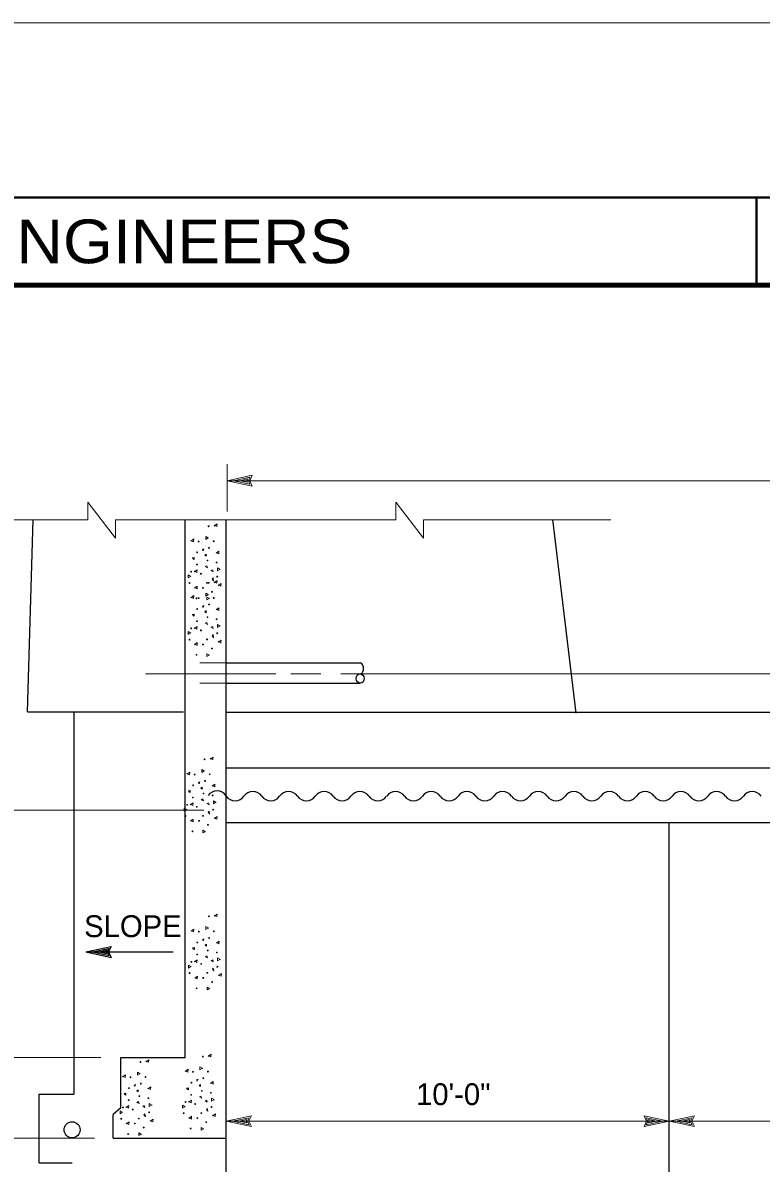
# Model space of a CAD drawing. Extents: x -24.3 to 17.7, y -17.6 to 12.4.
# Drawn here: x -19.54 to -15.32, y 5.87 to 12.39 of the extents above; entities that cross this region are included whole.
import ezdxf
from ezdxf.enums import TextEntityAlignment as Align

# ---------------------------------------------------------------- set-up
doc = ezdxf.new("R2010")
doc.units = 0
doc.header["$LTSCALE"] = 0.05
doc.linetypes.add('MEDIUM_DASHED', pattern=[4.5, 3, -1.5])
doc.layers.add('1', color=7, linetype='Continuous', lineweight=13)
doc.layers.add('2', color=7, linetype='Continuous', lineweight=13)

msp = doc.modelspace()

# ---------------------------------------------------------------- linework, layer by layer
at = {"layer": '1', "lineweight": 40}
msp.add_line((-15.34269, 11.3894), (-15.34269, 10.8894), dxfattribs=at)
at = {"layer": '1'}
for p, q in [((-18.37069, 9.5954), (-18.37069, 9.8654)), ((-18.37069, 9.7704), (-18.22669, 9.8014)), ((-18.33369, 9.7704), (-18.23969, 9.7904)), ((-18.23969, 9.7904), (-18.24869, 9.7704)), ((-18.37069, 9.7704), (-18.22669, 9.7394)), ((-18.37069, 9.7704), (-12.85569, 9.7704)), ((-18.33369, 9.7704), (-18.23969, 9.7504)), ((-18.29769, 9.7704), (-18.25269, 9.7804)), ((-18.29769, 9.7704), (-18.25269, 9.7614)), ((-18.25269, 9.7804), (-18.25669, 9.7704)), ((-18.25669, 9.7704), (-18.25269, 9.7614)), ((-18.24869, 9.7704), (-18.23969, 9.7504)), ((-19.16669, 9.5474), (-19.16669, 9.6474)), ((-19.00869, 9.4424), (-19.16669, 9.6474)), ((-17.40469, 9.5474), (-17.40469, 9.6474)), ((-17.24669, 9.4424), (-17.40469, 9.6474)), ((-19.72169, 9.5474), (-19.16669, 9.5474)), ((-19.00869, 9.4424), (-19.00869, 9.5474)), ((-19.00869, 9.5474), (-17.40469, 9.5474)), ((-17.24669, 9.4424), (-17.24669, 9.5474)), ((-17.24669, 9.5474), (-16.17469, 9.5474)), ((-18.83669, 8.6664), (-18.09169, 8.6664)), ((-18.00569, 8.6664), (-17.83369, 8.6664)), ((-17.71969, 8.6664), (-13.15669, 8.6664)), ((-18.50269, 7.8864), (-21.16869, 7.8864)), ((-19.09169, 6.4724), (-20.31569, 6.4724)), ((-18.37569, 6.1074), (-18.23169, 6.1384)), ((-15.84169, 6.1074), (-15.98569, 6.1384)), ((-15.84169, 6.1074), (-15.69769, 6.1384)), ((-18.37569, 6.1074), (-18.23169, 6.0764)), ((-18.33869, 6.1074), (-18.24469, 6.1274)), ((-18.33869, 6.1074), (-18.24469, 6.0874)), ((-18.30269, 6.1074), (-18.25769, 6.1174)), ((-18.30269, 6.1074), (-18.25769, 6.0984)), ((-18.25769, 6.1174), (-18.26169, 6.1074)), ((-18.26169, 6.1074), (-18.25769, 6.0984)), ((-18.24469, 6.1274), (-18.25369, 6.1074)), ((-18.25369, 6.1074), (-18.24469, 6.0874)), ((-15.84169, 6.1074), (-15.98569, 6.0764)), ((-15.87869, 6.1074), (-15.97269, 6.1274)), ((-15.96369, 6.1074), (-15.97269, 6.1274)), ((-15.87869, 6.1074), (-15.97269, 6.0874)), ((-15.97269, 6.0874), (-15.96369, 6.1074)), ((-15.91469, 6.1074), (-15.95969, 6.1164)), ((-15.95569, 6.1074), (-15.95969, 6.1164)), ((-15.91469, 6.1074), (-15.95969, 6.0974)), ((-15.95969, 6.0974), (-15.95569, 6.1074)), ((-15.84169, 6.1074), (-15.69769, 6.0764)), ((-15.80469, 6.1074), (-15.71069, 6.1274)), ((-15.80469, 6.1074), (-15.71069, 6.0874)), ((-15.76869, 6.1074), (-15.72369, 6.1174)), ((-15.76869, 6.1074), (-15.72369, 6.0984)), ((-15.72369, 6.1174), (-15.72769, 6.1074)), ((-15.72769, 6.1074), (-15.72369, 6.0984)), ((-15.71069, 6.1274), (-15.71969, 6.1074)), ((-15.71969, 6.1074), (-15.71069, 6.0874)), ((-19.12869, 6.0104), (-20.37669, 6.0104))]:
    msp.add_line(p, q, dxfattribs=at)
at = {"layer": '1', "lineweight": 25}
for p, q in [((-19.51169, 8.4484), (-19.47869, 9.5474)), ((-18.61069, 6.4724), (-18.61069, 9.5474)), ((-18.37569, -0.0986), (-18.37569, 9.5474)), ((-16.37369, 8.4404), (-16.50769, 9.5484)), ((-18.37569, 8.7284), (-17.60669, 8.7284)), ((-18.37569, 8.6124), (-17.60869, 8.6124)), ((-19.51169, 8.4484), (-18.61969, 8.4484)), ((-19.24569, 6.2664), (-19.24569, 8.4484)), ((-18.37569, 8.4474), (-9.74369, 8.4474)), ((-18.37569, 8.1284), (-9.77669, 8.1284)), ((-18.37569, 7.8164), (-9.81169, 7.8164)), ((-15.84269, 1.6534), (-15.84269, 7.8164)), ((-19.17769, 7.0754), (-19.03369, 7.1064)), ((-19.17769, 7.0754), (-18.67869, 7.0754)), ((-19.17769, 7.0754), (-19.03369, 7.0444)), ((-19.14069, 7.0754), (-19.04669, 7.0954)), ((-19.14069, 7.0754), (-19.04669, 7.0554)), ((-19.10469, 7.0754), (-19.05969, 7.0854)), ((-19.10469, 7.0754), (-19.05969, 7.0664)), ((-19.05969, 7.0854), (-19.06369, 7.0754)), ((-19.06369, 7.0754), (-19.05969, 7.0664)), ((-19.04669, 7.0954), (-19.05569, 7.0754)), ((-19.05569, 7.0754), (-19.04669, 7.0554)), ((-18.97769, 6.1834), (-18.97769, 6.4724)), ((-18.97769, 6.4724), (-18.61069, 6.4724)), ((-19.44569, 5.8694), (-19.44569, 6.2624)), ((-19.44569, 6.2624), (-19.24569, 6.2624)), ((-18.97769, 6.1834), (-19.02269, 6.1454)), ((-19.02269, 6.0104), (-19.02269, 6.1454)), ((-19.02269, 6.0104), (-18.37969, 6.0104)), ((-19.44569, 5.8694), (-19.25569, 5.8694))]:
    msp.add_line(p, q, dxfattribs=at)
at = {"layer": '1', "linetype": 'MEDIUM_DASHED'}
for p, q in [((-18.37569, 8.7284), (-18.61069, 8.7284)), ((-18.37569, 8.6124), (-18.61069, 8.6124))]:
    msp.add_line(p, q, dxfattribs=at)
at = {"layer": '1'}
for points in [[(-24.34269, 12.3894), (17.65731, 12.3894), (17.65731, -17.6106)], [(-18.22669, 9.8014), (-18.24069, 9.7704), (-18.22669, 9.7394)], [(-18.23169, 6.1384), (-18.24569, 6.1074), (-18.23169, 6.0764)], [(-15.98569, 6.0764), (-15.97169, 6.1074), (-15.98569, 6.1384)], [(-15.69769, 6.1384), (-15.71169, 6.1074), (-15.69769, 6.0764)], [(-18.37569, 6.1074), (-15.84169, 6.1074), (-10.82569, 6.1074)]]:
    msp.add_lwpolyline(points, dxfattribs=at)
at = {"layer": '1', "lineweight": 40}
msp.add_lwpolyline([(-23.34269, -16.6106), (-23.34269, 11.3894), (16.65731, 11.3894), (16.65731, -16.6106)], close=True, dxfattribs=at)
at = {"layer": '1', "lineweight": 90}
msp.add_lwpolyline([(-21.84269, 10.8894), (16.15731, 10.8894), (16.15731, -16.1106), (-21.84269, -16.1106)], close=True, dxfattribs=at)
at = {"layer": '1', "lineweight": 25}
msp.add_lwpolyline([(-19.03369, 7.1064), (-19.04769, 7.0754), (-19.03369, 7.0444)], dxfattribs=at)
msp.add_circle((-19.25669, 6.0584), 0.04597, dxfattribs=at)
for centre, radius, start, end in [((-17.62775, 8.69668), 0.03807, 307.28682, 56.4084), ((-18.42769, 7.9349), 0.06157, 34.07719, 145.9228), ((-18.32469, 8.0009), 0.06157, 214.07719, 325.9228), ((-18.22269, 7.9319), 0.06157, 34.07719, 145.9228), ((-18.12069, 8.0009), 0.06157, 214.07719, 325.9228), ((-18.01869, 7.9319), 0.06157, 34.07719, 145.9228), ((-17.91669, 8.0009), 0.06157, 214.07719, 325.9228), ((-17.81469, 7.9319), 0.06157, 34.07719, 145.9228), ((-17.71269, 8.0009), 0.06157, 214.07719, 325.9228), ((-17.61069, 7.9319), 0.06157, 34.07719, 145.9228), ((-17.50869, 8.0009), 0.06157, 214.07719, 325.9228), ((-17.40669, 7.9319), 0.06157, 34.07719, 145.9228), ((-17.30469, 8.0009), 0.06157, 214.07719, 325.9228), ((-17.20269, 7.9319), 0.06157, 34.07719, 145.9228), ((-17.10069, 8.0009), 0.06157, 214.07719, 325.9228), ((-16.99869, 7.9319), 0.06157, 34.07719, 145.9228), ((-16.89669, 8.0009), 0.06157, 214.07719, 325.9228), ((-16.79469, 7.9319), 0.06157, 34.07719, 145.9228), ((-16.69269, 8.0009), 0.06157, 214.07719, 325.9228), ((-16.59069, 7.9319), 0.06157, 34.07719, 145.9228), ((-16.48869, 8.0009), 0.06157, 214.07719, 325.9228), ((-16.38669, 7.9319), 0.06157, 34.07719, 145.9228), ((-16.28469, 8.0009), 0.06157, 214.07719, 325.9228), ((-16.18269, 7.9319), 0.06157, 34.07719, 145.9228), ((-16.08069, 8.0009), 0.06157, 214.07719, 325.9228), ((-15.97869, 7.9319), 0.06157, 34.07719, 145.9228), ((-15.87669, 8.0009), 0.06157, 214.07719, 325.9228), ((-15.77469, 7.9319), 0.06157, 34.07719, 145.9228), ((-15.67269, 8.0009), 0.06157, 214.07719, 325.9228), ((-15.57069, 7.9319), 0.06157, 34.07719, 145.9228), ((-15.46869, 8.0009), 0.06157, 214.07719, 325.9228), ((-15.36669, 7.9319), 0.06157, 34.07719, 145.9228)]:
    msp.add_arc(centre, radius, start, end, dxfattribs=at)
msp.add_ellipse((-17.60919, 8.6394), major_axis=(-0.0005, 0.027), ratio=0.833928, dxfattribs=at)
at = {"layer": '2'}
for p, q in [((-18.56069, 9.3204), (-18.56869, 9.3294)), ((-18.56069, 8.9964), (-18.56869, 9.0054)), ((-18.58369, 7.9874), (-18.59169, 7.9964)), ((-18.55969, 7.0894), (-18.56769, 7.0984)), ((-18.95069, 6.2564), (-18.95869, 6.2654)), ((-18.59369, 6.2874), (-18.60169, 6.2964))]:
    msp.add_line(p, q, dxfattribs=at)
for points in [[(-18.44469, 9.5154), (-18.42969, 9.5084), (-18.42769, 9.5234), (-18.44469, 9.5114)], [(-18.57769, 9.4294), (-18.56269, 9.4214), (-18.56069, 9.4374), (-18.57769, 9.4254)], [(-18.47969, 9.4424), (-18.49269, 9.4344), (-18.49269, 9.4514), (-18.47669, 9.4424)], [(-18.56969, 9.3294), (-18.55869, 9.3314), (-18.55869, 9.3204)], [(-18.50869, 9.3704), (-18.51169, 9.3774), (-18.50369, 9.3814), (-18.50769, 9.3704)], [(-18.48969, 9.3394), (-18.49669, 9.3444), (-18.48969, 9.3514), (-18.48869, 9.3404)], [(-18.43269, 9.3604), (-18.41769, 9.3524), (-18.41669, 9.3674), (-18.43269, 9.3564)], [(-18.55869, 9.2534), (-18.54369, 9.2464), (-18.54169, 9.2614), (-18.55869, 9.2494)], [(-18.41269, 9.2634), (-18.42569, 9.2554), (-18.42569, 9.2724), (-18.40969, 9.2634)], [(-18.57969, 9.2224), (-18.59269, 9.2144), (-18.59269, 9.2314), (-18.57769, 9.2224)], [(-18.45069, 9.2004), (-18.45569, 9.2074), (-18.45069, 9.2144), (-18.44769, 9.1964)], [(-18.44469, 9.1914), (-18.42969, 9.1844), (-18.42769, 9.1994), (-18.44469, 9.1874)], [(-18.55669, 9.1594), (-18.54169, 9.1524), (-18.54069, 9.1684), (-18.55669, 9.1564)], [(-18.42069, 9.1744), (-18.40569, 9.1674), (-18.40369, 9.1834), (-18.42069, 9.1714)], [(-18.57769, 9.1054), (-18.56269, 9.0974), (-18.56069, 9.1134), (-18.57769, 9.1014)], [(-18.47969, 9.1184), (-18.49269, 9.1104), (-18.49269, 9.1274), (-18.47669, 9.1184)], [(-18.47269, 9.0964), (-18.48569, 9.0894), (-18.48569, 9.1054), (-18.47069, 9.0964)], [(-18.56969, 9.0054), (-18.55869, 9.0074), (-18.55869, 8.9964)], [(-18.50869, 9.0464), (-18.51169, 9.0534), (-18.50369, 9.0574), (-18.50769, 9.0464)], [(-18.48969, 9.0154), (-18.49669, 9.0204), (-18.48969, 9.0274), (-18.48869, 9.0164)], [(-18.43269, 9.0364), (-18.41769, 9.0284), (-18.41669, 9.0434), (-18.43269, 9.0324)], [(-18.55869, 8.9294), (-18.54369, 8.9224), (-18.54169, 8.9374), (-18.55869, 8.9254)], [(-18.41269, 8.9394), (-18.42569, 8.9314), (-18.42569, 8.9484), (-18.40969, 8.9394)], [(-18.57969, 8.8984), (-18.59269, 8.8904), (-18.59269, 8.9074), (-18.57769, 8.8984)], [(-18.45069, 8.8764), (-18.45569, 8.8834), (-18.45069, 8.8904), (-18.44769, 8.8724)], [(-18.55669, 8.8354), (-18.54169, 8.8284), (-18.54069, 8.8444), (-18.55669, 8.8324)], [(-18.42069, 8.8504), (-18.40569, 8.8434), (-18.40369, 8.8594), (-18.42069, 8.8474)], [(-18.47269, 8.7724), (-18.48569, 8.7654), (-18.48569, 8.7814), (-18.47069, 8.7724)], [(-18.46769, 8.1824), (-18.45269, 8.1754), (-18.45069, 8.1904), (-18.46769, 8.1784)], [(-18.60069, 8.0964), (-18.58569, 8.0884), (-18.58369, 8.1044), (-18.60069, 8.0924)], [(-18.50269, 8.1094), (-18.51569, 8.1014), (-18.51569, 8.1184), (-18.49969, 8.1094)], [(-18.53169, 8.0374), (-18.53469, 8.0444), (-18.52669, 8.0484), (-18.53069, 8.0374)], [(-18.45569, 8.0274), (-18.44069, 8.0194), (-18.43969, 8.0344), (-18.45569, 8.0234)], [(-18.59269, 7.9964), (-18.58169, 7.9984), (-18.58169, 7.9874)], [(-18.51269, 8.0064), (-18.51969, 8.0114), (-18.51269, 8.0184), (-18.51169, 8.0074)], [(-18.60269, 7.8894), (-18.61569, 7.8814), (-18.61569, 7.8984), (-18.60069, 7.8894)], [(-18.58169, 7.9204), (-18.56669, 7.9134), (-18.56469, 7.9284), (-18.58169, 7.9164)], [(-18.43569, 7.9304), (-18.44869, 7.9224), (-18.44869, 7.9394), (-18.43269, 7.9304)], [(-18.57969, 7.8264), (-18.56469, 7.8194), (-18.56369, 7.8354), (-18.57969, 7.8234)], [(-18.47369, 7.8674), (-18.47869, 7.8744), (-18.47369, 7.8814), (-18.47069, 7.8634)], [(-18.44369, 7.8414), (-18.42869, 7.8344), (-18.42669, 7.8504), (-18.44369, 7.8384)], [(-18.49569, 7.7634), (-18.50869, 7.7564), (-18.50869, 7.7724), (-18.49369, 7.7634)], [(-18.44369, 7.2844), (-18.42869, 7.2774), (-18.42669, 7.2924), (-18.44369, 7.2804)], [(-18.57669, 7.1984), (-18.56169, 7.1904), (-18.55969, 7.2064), (-18.57669, 7.1944)], [(-18.47869, 7.2114), (-18.49169, 7.2034), (-18.49169, 7.2204), (-18.47569, 7.2114)], [(-18.50769, 7.1394), (-18.51069, 7.1464), (-18.50269, 7.1504), (-18.50669, 7.1394)], [(-18.48869, 7.1084), (-18.49569, 7.1134), (-18.48869, 7.1204), (-18.48769, 7.1094)], [(-18.43169, 7.1294), (-18.41669, 7.1214), (-18.41569, 7.1364), (-18.43169, 7.1254)], [(-18.56869, 7.0984), (-18.55769, 7.1004), (-18.55769, 7.0894)], [(-18.57869, 6.9914), (-18.59169, 6.9834), (-18.59169, 7.0004), (-18.57669, 6.9914)], [(-18.55769, 7.0224), (-18.54269, 7.0154), (-18.54069, 7.0304), (-18.55769, 7.0184)], [(-18.44969, 6.9694), (-18.45469, 6.9764), (-18.44969, 6.9834), (-18.44669, 6.9654)], [(-18.41169, 7.0324), (-18.42469, 7.0244), (-18.42469, 7.0414), (-18.40869, 7.0324)], [(-18.55569, 6.9284), (-18.54069, 6.9214), (-18.53969, 6.9374), (-18.55569, 6.9254)], [(-18.41969, 6.9434), (-18.40469, 6.9364), (-18.40269, 6.9524), (-18.41969, 6.9404)], [(-18.47169, 6.8654), (-18.48469, 6.8584), (-18.48469, 6.8744), (-18.46969, 6.8654)], [(-18.83469, 6.4514), (-18.81969, 6.4444), (-18.81769, 6.4594), (-18.83469, 6.4474)], [(-18.47769, 6.4824), (-18.46269, 6.4754), (-18.46069, 6.4904), (-18.47769, 6.4784)], [(-18.61069, 6.3964), (-18.59569, 6.3884), (-18.59369, 6.4044), (-18.61069, 6.3924)], [(-18.51269, 6.4094), (-18.52569, 6.4014), (-18.52569, 6.4184), (-18.50969, 6.4094)], [(-18.96769, 6.3654), (-18.95269, 6.3574), (-18.95069, 6.3734), (-18.96769, 6.3614)], [(-18.86969, 6.3784), (-18.88269, 6.3704), (-18.88269, 6.3874), (-18.86669, 6.3784)], [(-18.54169, 6.3374), (-18.54469, 6.3444), (-18.53669, 6.3484), (-18.54069, 6.3374)], [(-18.46569, 6.3274), (-18.45069, 6.3194), (-18.44969, 6.3344), (-18.46569, 6.3234)], [(-18.95969, 6.2654), (-18.94869, 6.2674), (-18.94869, 6.2564)], [(-18.89869, 6.3064), (-18.90169, 6.3134), (-18.89369, 6.3174), (-18.89769, 6.3064)], [(-18.87969, 6.2754), (-18.88669, 6.2804), (-18.87969, 6.2874), (-18.87869, 6.2764)], [(-18.82269, 6.2964), (-18.80769, 6.2884), (-18.80669, 6.3034), (-18.82269, 6.2924)], [(-18.60269, 6.2964), (-18.59169, 6.2984), (-18.59169, 6.2874)], [(-18.52269, 6.3064), (-18.52969, 6.3114), (-18.52269, 6.3184), (-18.52169, 6.3074)], [(-18.94869, 6.1894), (-18.93369, 6.1824), (-18.93169, 6.1974), (-18.94869, 6.1854)], [(-18.80269, 6.1994), (-18.81569, 6.1914), (-18.81569, 6.2084), (-18.79969, 6.1994)], [(-18.61269, 6.1894), (-18.62569, 6.1814), (-18.62569, 6.1984), (-18.61069, 6.1894)], [(-18.59169, 6.2204), (-18.57669, 6.2134), (-18.57469, 6.2284), (-18.59169, 6.2164)], [(-18.44569, 6.2304), (-18.45869, 6.2224), (-18.45869, 6.2394), (-18.44269, 6.2304)], [(-18.96969, 6.1584), (-18.98269, 6.1504), (-18.98269, 6.1674), (-18.96769, 6.1584)], [(-18.84069, 6.1364), (-18.84569, 6.1434), (-18.84069, 6.1504), (-18.83769, 6.1324)], [(-18.58969, 6.1264), (-18.57469, 6.1194), (-18.57369, 6.1354), (-18.58969, 6.1234)], [(-18.48369, 6.1674), (-18.48869, 6.1744), (-18.48369, 6.1814), (-18.48069, 6.1634)], [(-18.45369, 6.1414), (-18.43869, 6.1344), (-18.43669, 6.1504), (-18.45369, 6.1384)], [(-18.94669, 6.0954), (-18.93169, 6.0884), (-18.93069, 6.1044), (-18.94669, 6.0924)], [(-18.81069, 6.1104), (-18.79569, 6.1034), (-18.79369, 6.1194), (-18.81069, 6.1074)], [(-18.50569, 6.0634), (-18.51869, 6.0564), (-18.51869, 6.0724), (-18.50369, 6.0634)], [(-18.86269, 6.0324), (-18.87569, 6.0254), (-18.87569, 6.0414), (-18.86069, 6.0324)]]:
    msp.add_lwpolyline(points, dxfattribs=at)
for points in [[(-18.48269, 9.2724), (-18.49569, 9.2794), (-18.48669, 9.2834)], [(-18.45069, 9.2494), (-18.46269, 9.2574), (-18.45369, 9.2614)], [(-18.48269, 8.9484), (-18.49569, 8.9554), (-18.48669, 8.9594)], [(-18.45069, 8.9254), (-18.46269, 8.9334), (-18.45369, 8.9374)], [(-18.50569, 7.9394), (-18.51869, 7.9464), (-18.50969, 7.9504)], [(-18.47369, 7.9164), (-18.48569, 7.9244), (-18.47669, 7.9284)], [(-18.48169, 7.0414), (-18.49469, 7.0484), (-18.48569, 7.0524)], [(-18.44969, 7.0184), (-18.46169, 7.0264), (-18.45269, 7.0304)], [(-18.87269, 6.2084), (-18.88569, 6.2154), (-18.87669, 6.2194)], [(-18.84069, 6.1854), (-18.85269, 6.1934), (-18.84369, 6.1974)], [(-18.51569, 6.2394), (-18.52869, 6.2464), (-18.51969, 6.2504)], [(-18.48369, 6.2164), (-18.49569, 6.2244), (-18.48669, 6.2284)]]:
    msp.add_lwpolyline(points, close=True, dxfattribs=at)
for centre in [(-18.47612, 9.51015), (-18.53275, 9.42277), (-18.44687, 9.42427), (-18.54137, 9.3609), (-18.4735, 9.3864), (-18.54287, 9.29152), (-18.48212, 9.3144), (-18.43037, 9.30315), (-18.5755, 9.2499), (-18.52, 9.23865), (-18.42662, 9.22215), (-18.58563, 9.18577), (-18.50763, 9.15802), (-18.48475, 9.1869), (-18.47612, 9.18615), (-18.457, 9.13515), (-18.5455, 9.0984), (-18.53275, 9.09877), (-18.44687, 9.10027), (-18.54137, 9.0369), (-18.4735, 9.0624), (-18.54287, 8.96752), (-18.48212, 8.9904), (-18.43037, 8.97915), (-18.5755, 8.9259), (-18.52, 8.91465), (-18.42662, 8.89815), (-18.58563, 8.86177), (-18.50763, 8.83402), (-18.48475, 8.8629), (-18.457, 8.81115), (-18.5455, 8.7744), (-18.49912, 8.17715), (-18.55575, 8.08977), (-18.46987, 8.09127), (-18.56437, 8.0279), (-18.4965, 8.0534), (-18.56587, 7.95852), (-18.50512, 7.9814), (-18.45337, 7.97015), (-18.5985, 7.9169), (-18.543, 7.90565), (-18.60862, 7.85277), (-18.53063, 7.82502), (-18.50775, 7.8539), (-18.44963, 7.88915), (-18.5685, 7.7654), (-18.48, 7.80215), (-18.47512, 7.27915), (-18.53175, 7.19177), (-18.44588, 7.19327), (-18.54038, 7.1299), (-18.4725, 7.1554), (-18.54188, 7.06052), (-18.48112, 7.0834), (-18.42938, 7.07215), (-18.5745, 7.0189), (-18.519, 7.00765), (-18.42563, 6.99115), (-18.58462, 6.95477), (-18.50662, 6.92702), (-18.48375, 6.9559), (-18.5445, 6.8674), (-18.456, 6.90415), (-18.50913, 6.47715), (-18.86613, 6.44615), (-18.56575, 6.38977), (-18.47987, 6.39127), (-18.92275, 6.35877), (-18.83687, 6.36027), (-18.57437, 6.3279), (-18.5065, 6.3534), (-18.93137, 6.2969), (-18.8635, 6.3224), (-18.51512, 6.2814), (-18.46337, 6.27015), (-18.93287, 6.22752), (-18.87213, 6.2504), (-18.82037, 6.23915), (-18.6085, 6.2169), (-18.57587, 6.25852), (-18.553, 6.20565), (-18.9655, 6.1859), (-18.91, 6.17465), (-18.81662, 6.15815), (-18.61862, 6.15277), (-18.51775, 6.1539), (-18.45962, 6.18915), (-18.97563, 6.12177), (-18.89762, 6.09402), (-18.87475, 6.1229), (-18.847, 6.07115), (-18.5785, 6.0654), (-18.54062, 6.12502), (-18.49, 6.10215), (-18.9355, 6.0344)]:
    msp.add_circle(centre, 0.00244, dxfattribs=at)

# ---------------------------------------------------------------- texts
at = {"layer": '1', "width": 1.1}
msp.add_text('CORPS OF ENGINEERS', height=0.25, dxfattribs=at).set_placement((-21.84269, 11.0144))
at = {"layer": '1'}
for s, p in [('SLOPE', (-18.90919, 7.1604)), ('10\'-0"', (-17.07669, 6.1994))]:
    msp.add_text(s, height=0.125, dxfattribs=at).set_placement(p, align=Align.CENTER)

doc.saveas('drawing.dxf')
